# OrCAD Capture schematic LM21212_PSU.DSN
size A
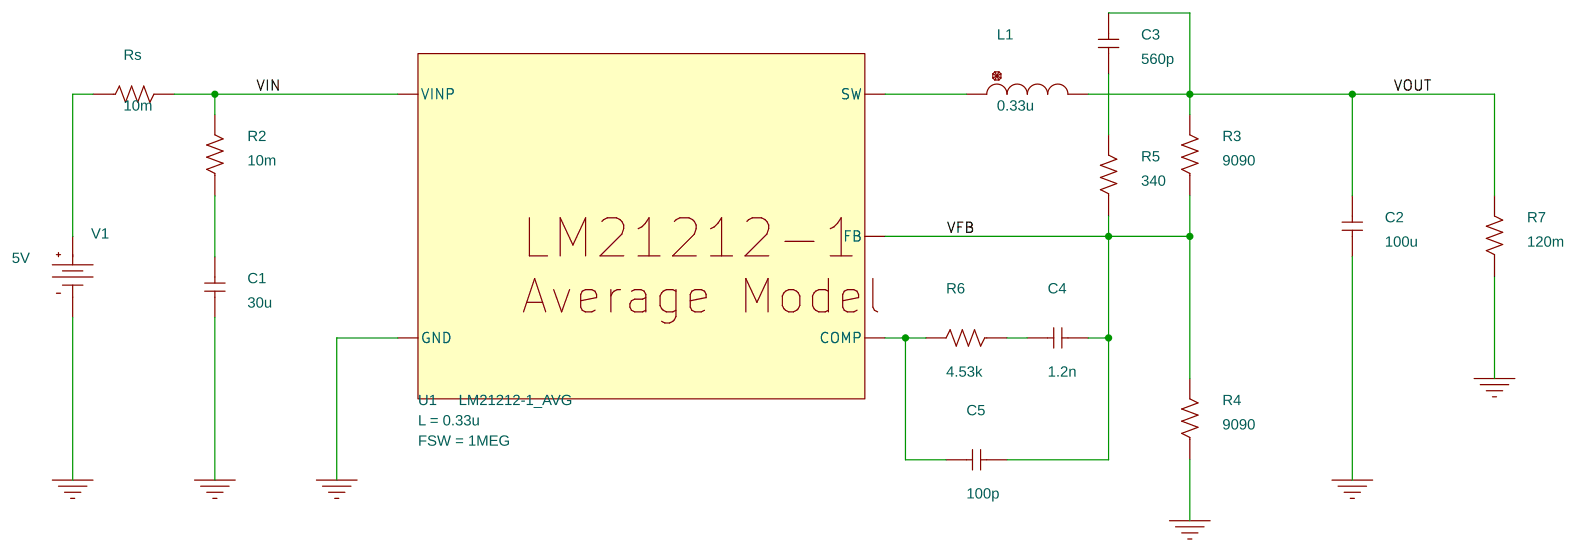
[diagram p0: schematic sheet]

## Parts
C1  30u  [cap196]
C2  100u  [cap196]
C3  560p  [cap196]
C4  1.2n  [cap196]
C5  100p  [cap196]
L1  0.33u  [DISC350x175LS200x100034]
R2  10m  [AXRC05]
R3  9090  [AXRC05]
R4  9090  [AXRC05]
R5  340  [AXRC05]
R6  4.53k  [AXRC05]
R7  120m  [AXRC05]
Rs  10m  [AXRC05]
U1  LM21212-1_AVG
V1  VDC

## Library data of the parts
C1-C5 = C
L1 = L
R2-R7 Rs = R
U1 = LM21212-1_AVG: FSW: 1MEG; L: 0.33u
V1 = VDC: DC: 5V

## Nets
VIN: R2.2 Rs.2 U1.VINP
0: C1.1 C2.1 R4.1 R7.1 U1.GND V1.1(-)
VFB: C4.1 C5.1 R3.1 R4.2 R5.1 U1.FB
VOUT: C2.2 C3.2 L1.2 R3.2 R7.2
N00147: Rs.1 V1.0(+)
N00250: C1.2 R2.1
N00351: L1.1 U1.SW
N00586: C3.1 R5.2
N00643: C5.2 R6.2 U1.COMP
N00677: C4.2 R6.1
